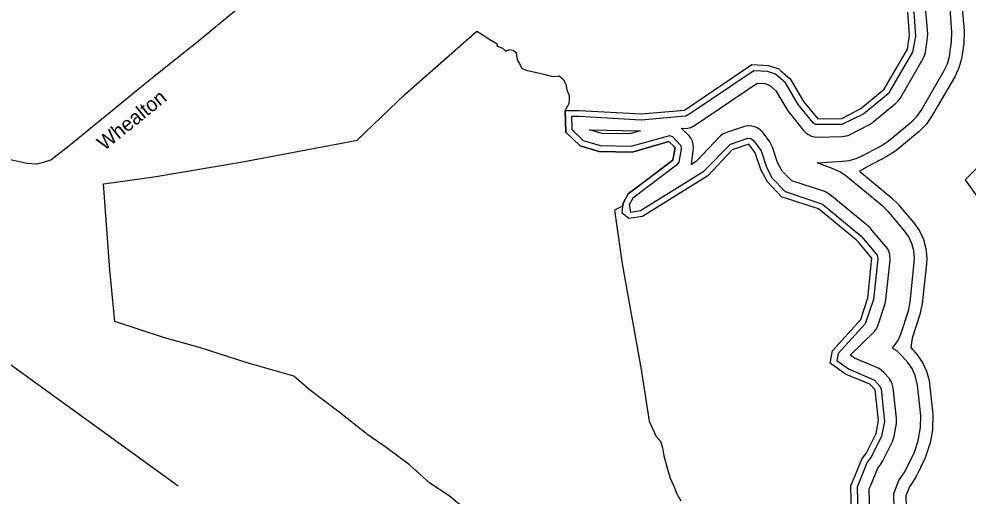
# Model space of a CAD drawing. Extents: x 2532689 to 2764727, y 536648 to 732970.
# Drawn here: x 2703526 to 2709761, y 575110 to 578243 of the extents above; entities that cross this region are included whole.
import ezdxf

# ---------------------------------------------------------------- set-up
doc = ezdxf.new("R2010")
doc.units = 0
for name, color, linetype in [('Exist Boundary Land Use Gamelands State NC Wildlife Resources Commission', 7, 'Continuous'), ('Exist Hydrographic Buffer Line', 7, 'Continuous'), ('Exist Hydrographic River Shore', 7, 'Continuous'), ('Exist Road Secondary Structure Pipe Number Label', 7, 'Continuous'), ('Exist Road Secondary Type 51 Attributed', 7, 'Continuous'), ('Exist Road Secondary Type 51 Label', 7, 'Continuous')]:
    doc.layers.add(name, color=color, linetype=linetype)

msp = doc.modelspace()

# ---------------------------------------------------------------- linework, layer by layer
at = {"layer": 'Exist Boundary Land Use Gamelands State NC Wildlife Resources Commission'}
msp.add_lwpolyline([(2706443.9, 575033.6), (2706351, 575110.4), (2706224.1, 575194.8), (2706090.8, 575315.1), (2705939.3, 575429.3), (2705818.3, 575511.7), (2705630.5, 575661.4), (2705432.8, 575809), (2705331.7, 575897.7), (2705024.7, 575983.8), (2704717.6, 576083.9), (2704474.8, 576150.8), (2704155.5, 576256.7), (2704123.3, 576596.6), (2704082.3, 577160.3), (2704411.8, 577206.5), (2704982.5, 577302), (2705644.8, 577426.6), (2705748.6, 577448), (2706062.7, 577750.2), (2706533.5, 578162.5), (2706562.4, 578144.8), (2706620.2, 578109.5), (2706666.6, 578080.2), (2706664.7, 578066.1), (2706703.1, 578050.6), (2706725, 578032.9), (2706749, 578043.2), (2706773, 578039.5), (2706791.3, 578023.7), (2706793.5, 578003.7), (2706799.7, 577975.8), (2706814, 577948), (2706830.4, 577920.1), (2706858.5, 577906.5), (2706926.8, 577891.4), (2706972.9, 577879.9), (2707023, 577866.6), (2707052.9, 577864.9), (2707075, 577869.3), (2707101.3, 577847.6), (2707117.7, 577815.8), (2707124.3, 577777.8), (2707140.5, 577740), (2707141.1, 577716), (2707137.2, 577686), (2707120.6, 577654.4), (2707114.2, 577641.9), (2707118.3, 577500.8), (2707212.2, 577409.4), (2707338.3, 577371.8), (2707554.3, 577367.4), (2707794.2, 577439.4), (2707837.2, 577398.5), (2707822.3, 577315.8), (2707760.7, 577269.6), (2707613.7, 577158.8), (2707527.2, 577093.8), (2707495.2, 577033.4), (2707493.8, 577015.8), (2707469.6, 577001.9), (2707437.8, 576987.4), (2707488.2, 576633.9), (2707612.7, 575941.1), (2707666.8, 575601.6), (2707711.9, 575500.2), (2707740.4, 575470.5), (2707753, 575426.6), (2707761.6, 575372.8), (2707786.8, 575287), (2707803.6, 575227.2), (2707828, 575173.5), (2707846.7, 575123.6), (2707873.3, 575077.9)], dxfattribs=at)
at = {"layer": 'Exist Hydrographic Buffer Line'}
for points in [[(2709404, 578290.8), (2709415.7, 578131), (2709396.9, 578024.4), (2709235.7, 577751.4), (2709075.5, 577620.5), (2708932, 577550.4), (2708759.6, 577549.7), (2708742.3, 577561.9), (2708644.7, 577681.3), (2708561.1, 577823.4), (2708496.7, 577879.9), (2708442.5, 577899), (2708352.5, 577903.6), (2707920.7, 577610.8), (2707901.8, 577604.1), (2707613.1, 577579.4), (2707205.3, 577602.2), (2707155.6, 577602.1), (2707157.9, 577518.2), (2707233.1, 577444.9), (2707344.5, 577411.6), (2707548.7, 577407.5), (2707801.3, 577478.8), (2707821.8, 577468.4), (2707874.8, 577412.2), (2707876.6, 577391.4), (2707859.8, 577302.1), (2707846.2, 577283.9), (2707558.6, 577067.1), (2707534.4, 577021.7), (2707543, 576975.2), (2707608.4, 576984.9), (2708024.8, 577244.6), (2708199.3, 577421.8), (2708313.4, 577460.6), (2708334.1, 577458.8), (2708352.3, 577445.2), (2708401.3, 577376.3), (2708436.2, 577269.4), (2708474.9, 577197.1), (2708560.4, 577109.6), (2708804.9, 577027.3), (2709056.9, 576818.8), (2709070.8, 576802.4), (2709164.1, 576692.4), (2709169, 576668.3), (2709140.3, 576399.7), (2709085.8, 576241.8), (2708906.6, 576045.8), (2708898.4, 575999.7), (2708975.5, 575945.5), (2709146.1, 575871.1), (2709181.1, 575832.1), (2709190, 575810.8), (2709211.7, 575600.1), (2709193, 575503.3), (2709125.8, 575368.9), (2709097.3, 575332.7), (2709031.5, 575168.8), (2709040.3, 574809.6)], [(2708375.3, 577822.3), (2708426.8, 577819.7), (2708455.5, 577809.6), (2708498.5, 577771.7), (2708576, 577640.7), (2708680.6, 577511.1), (2708696, 577495.4), (2708713.2, 577483.4), (2708732.3, 577474.5), (2708752.6, 577469.1), (2708773.3, 577467.3), (2708933.4, 577470.3), (2708972.2, 577477.6), (2709112.4, 577549.6), (2709133.4, 577563.3), (2709286.5, 577689.6), (2709302.3, 577705.1), (2709314, 577722), (2709466, 577984.3), (2709475, 578003.4), (2709480.5, 578023.7), (2709495.1, 578119), (2709495.7, 578146.6), (2709483.8, 578297.1)], [(2709280.4, 574815.4), (2709272.6, 575125.3), (2709307.2, 575211.4), (2709345.4, 575269.5), (2709408.3, 575396.9), (2709432.9, 575472.9), (2709448.1, 575558.8), (2709450.6, 575637.6), (2709428.6, 575837.1), (2709413.3, 575902.2), (2709392.8, 575946.4), (2709364.9, 575986.4), (2709325.1, 576031.1), (2709296.4, 576058.9), (2709264.2, 576081.3), (2709298.8, 576128.8), (2709319.3, 576173.1), (2709368.8, 576326.2), (2709380.9, 576383), (2709407.7, 576643.5), (2709409.4, 576672.4), (2709405.1, 576721), (2709392.3, 576768.1), (2709371.8, 576812.4), (2709343.7, 576852.4), (2709253.5, 576958), (2709239.8, 576974.1), (2709204.3, 577009.1), (2708957.2, 577212.6), (2708919.3, 577239), (2708875, 577259.6), (2708770.2, 577299), (2708936.7, 577310.4), (2708979.8, 577314.6), (2709026.9, 577327.2), (2709060.8, 577342.1), (2709186.5, 577407.7), (2709235.1, 577439.8), (2709388.2, 577566.1), (2709424.7, 577602.2), (2709452.4, 577641.8), (2709604.6, 577904), (2709625.3, 577948.7), (2709638, 577995.8), (2709653, 578095.1), (2709655.2, 578159.2), (2709643.3, 578309.8)], [(2709723.1, 578316.2), (2709735, 578165.6), (2709732.3, 578083.1), (2709716.7, 577981.9), (2709700.5, 577921.4), (2709673.7, 577864), (2709521.7, 577601.7), (2709486.1, 577550.8), (2709439.3, 577504.3), (2709285.9, 577378.1), (2709223.6, 577336.9), (2709097.7, 577271.2), (2709046.8, 577242.6), (2709255.4, 577070.9), (2709300.7, 577025.9), (2709314.2, 577009.9), (2709405.1, 576903.8), (2709440.9, 576852.4), (2709467.6, 576795.5), (2709483.8, 576734.9), (2709489.3, 576672.4), (2709487.3, 576635.3), (2709460.2, 576374.7), (2709445, 576301.7), (2709394.6, 576145.7), (2709384.6, 576084.4), (2709426, 576037.7), (2709462.1, 575986.4), (2709488.5, 575929.5), (2709504.7, 575868.9), (2709508, 575845.9), (2709530.1, 575646.5), (2709527.1, 575545.1), (2709512.1, 575459.1), (2709480.1, 575361.4), (2709416.9, 575234), (2709377, 575170.9), (2709353, 575110.8), (2709360.4, 574817.4)], [(2709120.2, 574811.6), (2709111.8, 575154.3), (2709167.2, 575292.3), (2709188.5, 575319.4), (2709201.8, 575340.5), (2709264.8, 575467.8), (2709275.5, 575500.4), (2709290.6, 575586.3), (2709291.5, 575620.2), (2709269.5, 575819.6), (2709263, 575847.5), (2709254.3, 575866.4), (2709242.2, 575883.5), (2709205.7, 575924.4), (2709176.2, 575948.3), (2709014.2, 576016.2), (2708986.1, 576035.9), (2709144.8, 576187.9), (2709160.2, 576208.8), (2709169, 576227.8), (2709216.6, 576375.2), (2709221.5, 576399.5), (2709248.6, 576660), (2709247.6, 576693.2), (2709242, 576713.4), (2709233.2, 576732.4), (2709221.3, 576749.5), (2709131.5, 576854.3), (2709117.8, 576870.6), (2709102.6, 576885.6), (2708855.5, 577089.1), (2708820.2, 577109.2), (2708602.1, 577180.2), (2708540.4, 577244.5), (2708510, 577301), (2708477.2, 577401.1), (2708459.4, 577435.8), (2708416.3, 577493.2), (2708397.4, 577513.2), (2708380.2, 577525.2), (2708361.3, 577534), (2708341, 577539.4), (2708320.3, 577541.2), (2708299.6, 577539.4), (2708173.3, 577497.5), (2708152.2, 577488), (2708135, 577476), (2707973.8, 577307.1), (2707944.1, 577288.5), (2707955.3, 577377), (2707957.2, 577398.5), (2707955.5, 577419.3), (2707950, 577439.6), (2707941.2, 577458.5), (2707929.3, 577475.6), (2707877, 577526.4), (2707908.8, 577524.4), (2707939.3, 577531.2), (2707958.2, 577540), (2708375.3, 577822.3)], [(2707537.9, 577487.8), (2707357, 577491.4), (2707274.8, 577516), (2707606.1, 577508), (2707537.9, 577487.8)], [(2709823, 577268), (2709741.5, 577187.2), (2709821.9, 577072.4)]]:
    msp.add_lwpolyline(points, dxfattribs=at)
at = {"layer": 'Exist Hydrographic River Shore'}
for points in [[(2709057.1, 577656), (2709210.3, 577782.2), (2709362.2, 578044.5), (2709376.3, 578137), (2709364.2, 578287.5)], [(2708548.3, 577071.5), (2708536.2, 577075.4), (2708442.3, 577173.4), (2708399.3, 577253.7), (2708363.2, 577363.9), (2708320.3, 577421.2), (2708212.3, 577384.1), (2708050.3, 577213.3), (2707622.3, 576946.5), (2707531.3, 576933), (2707489.3, 576967.5), (2707495.2, 577033.4), (2707527.4, 577093.8), (2707822.3, 577315.8), (2707837.2, 577398.5), (2707794.4, 577439.4), (2707554.3, 577367.4), (2707338.3, 577371.8), (2707212.2, 577409.4), (2707118.3, 577500.8), (2707114.2, 577641.9), (2707206.3, 577642.3), (2707615.4, 577619.4), (2707898.3, 577643.9), (2708341.2, 577944.2), (2708450.3, 577938.7), (2708517.2, 577915.1), (2708528.3, 577905.5)], [(2708528.3, 577905.5), (2708592.2, 577849.2), (2708679.2, 577701.7), (2708773.3, 577587.3), (2708931.2, 577590.3), (2709057.1, 577656)], [(2709040.3, 576776.4), (2709026.3, 576793), (2708779.2, 576996.5), (2708548.3, 577071.5)], [(2708716.5, 574248.1), (2708796.3, 574278.4), (2708950.2, 574448.7), (2709005.4, 574602), (2709000.3, 574808.7), (2708991.3, 575176.1), (2709062.2, 575352.9), (2709094.2, 575393.6), (2709157.4, 575521), (2709172.3, 575606.9), (2709150.4, 575806.4), (2709116.3, 575844.4), (2708956.2, 575910.2), (2708854.3, 575981.6), (2708869.3, 576064.2), (2709056.3, 576268.8), (2709102.2, 576411.9), (2709129.3, 576672.4), (2709040.3, 576776.4)]]:
    msp.add_lwpolyline(points, dxfattribs=at)
at = {"layer": 'Exist Road Secondary Structure Pipe Number Label'}
msp.add_lwpolyline([(2700062.7, 579994.2), (2700416.3, 578181.9), (2704571.5, 575176)], dxfattribs=at)
at = {"layer": 'Exist Road Secondary Type 51 Attributed'}
msp.add_lwpolyline([(2703334.3, 577348.5), (2703420.1, 577332.2), (2703576.9, 577296.7), (2703642, 577292.2), (2703689.4, 577302.6), (2703735.2, 577318.9), (2703853.6, 577410.7), (2704404, 577859.2), (2704716.2, 578109.4), (2704920.4, 578276.7), (2705543.7, 578779.3), (2705673.5, 578897), (2707028.7, 579989.6)], dxfattribs=at)

# ---------------------------------------------------------------- texts
at = {"layer": 'Exist Road Secondary Type 51 Label'}
msp.add_text('Whealton', height=95, rotation=38.90099, dxfattribs=at).set_placement((2704087.1, 577374.7))

doc.saveas('drawing.dxf')
